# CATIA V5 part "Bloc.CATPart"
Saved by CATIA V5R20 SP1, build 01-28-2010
Part number: Bloc
Bounding box of the stored display mesh (mm): x -115 to 115, y -115 to 115, z -20 to 0
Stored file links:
  C:\Users\Nikow\Documents\IAO\Bloc.CATPart
  C:\Users\Nikow\Documents\IAO\Mecanisme_a_bielle_et_deux_coulisseaux.CATProduct
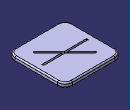
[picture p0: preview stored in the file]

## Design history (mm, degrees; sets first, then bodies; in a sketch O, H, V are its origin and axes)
External parameters (linked from other documents)
  External.Longueur_gliss = 170 mm
  External.Largeur = 7 mm
  External.Epaisseur = 20 mm
Set1
  Plane1 "Plan_de_ref": linked copy from another document
  Point1 to Point4: linked copy from another document
Body1 (main body)
  Sketch1 on Plane1, origin (0, 0, 0), H (1, 0, 0), V (0, 1, 0)
    line L1 (-115, -85) -> (-115, 85)
    arc A1 centre (-85, 85) radius 30 from (-115, 85) to (-85, 115) cw
    line L2 (-85, 115) -> (85, 115)
    arc A2 centre (85, 85) radius 30 from (85, 115) to (115, 85) cw
    line L3 (115, 85) -> (115, -85)
    arc A3 centre (85, -85) radius 30 from (115, -85) to (85, -115) cw
    line L4 (85, -115) -> (-85, -115)
    arc A4 centre (-85, -85) radius 30 from (-85, -115) to (-115, -85) cw
    point P13 (-88, 3.5)
    line L5 (-88, 3.5) -> (-8.4497, 3.5)
    line L6 (-8.4497, 3.5) -> (-64.7003, 59.7505)
    point P15 (-64.7003, 59.7505)
    point P16 (-59.7505, 64.7003)
    line L7 (-59.7505, 64.7003) -> (1.4497, 3.5)
    line L8 (1.4497, 3.5) -> (88, 3.5)
    point P18 (88, 3.5)
    point P19 (88, -3.5)
    line L9 (88, -3.5) -> (8.4497, -3.5)
    line L10 (8.4497, -3.5) -> (64.7003, -59.7505)
    point P21 (64.7003, -59.7505)
    point P22 (59.7505, -64.7003)
    line L11 (59.7505, -64.7003) -> (-1.4497, -3.5)
    line L12 (-1.4497, -3.5) -> (-88, -3.5)
    point P24 (-88, -3.5)
    arc A5 centre (-63.2861, 61.1647) radius 2 from (-64.7003, 62.579) to (-64.7003, 59.7505) ccw
    point P27 (-64.7003, 59.7505)
    line L13 (-64.7003, 62.579) -> (-62.579, 64.7003)
    arc A6 centre (-61.1647, 63.2861) radius 2 from (-59.7505, 64.7003) to (-62.579, 64.7003) ccw
    point P30 (-59.7505, 64.7003)
    reference projected point E1 (-60.1041, 60.1041) from Point2
    line L14 (64.7003, -62.579) -> (62.579, -64.7003)
    arc A7 centre (61.1647, -63.2861) radius 2 from (62.579, -64.7003) to (59.7505, -64.7003) cw
    point P34 (59.7505, -64.7003)
    arc A8 centre (63.2861, -61.1647) radius 2 from (64.7003, -62.579) to (64.7003, -59.7505) ccw
    point P36 (64.7003, -59.7505)
    reference projected point E2 (60.1041, -60.1041) from Point4
    arc A9 centre (88, 1.5) radius 2 from (90, 1.5) to (88, 3.5) ccw
    point P39 (88, 3.5)
    line L15 (90, 1.5) -> (90, -1.5)
    arc A10 centre (88, -1.5) radius 2 from (88, -3.5) to (90, -1.5) ccw
    point P42 (88, -3.5)
    reference projected point E3 (85, 0) from Point3
    arc A11 centre (-88, 1.5) radius 2 from (-88, 3.5) to (-90, 1.5) ccw
    point P44 (-88, 3.5)
    line L16 (-90, 1.5) -> (-90, -1.5)
    arc A12 centre (-88, -1.5) radius 2 from (-90, -1.5) to (-88, -3.5) ccw
    point P48 (-88, -3.5)
    reference projected point E4 (-85, 0) from Point1
    length L2 = 170 {= External.Longueur_gliss}
    length L3 = 170 {= External.Longueur_gliss}
    radius A2 = 30
    radius A1 = 30
    length L1 = 170 {= External.Longueur_gliss}
    length L4 = 170 {= External.Longueur_gliss}
    radius A4 = 30
    radius A3 = 30
    distance L1 V = 115 {= External.Longueur_gliss/2 +30mm}
    distance L2 H = 115 {= External.Longueur_gliss /2+30mm}
    distance L12 L5 = 7 {= External.Largeur}
    distance L8 L9 = 7 {= External.Largeur}
    distance L10 L11 = 7 {= External.Largeur}
    distance L7 L6 = 7 {= External.Largeur}
    radius A6 = 2
    radius A5 = 2
    distance E1 L13 = 5
    radius A8 = 2
    radius A7 = 2
    distance E2 L14 = 5
    radius A10 = 2
    radius A9 = 2
    distance E3 L15 = 5
    radius A12 = 2
    radius A11 = 2
    distance L16 E4 = 5
    vertical: L1 V
    tangency: A1 L1, L2 A1, A2 L2, L3 A2, A3 L3, L4 A3, A4 L1, A4 L4, L13 A6, A6 L7, A5 L13, A5 L6, A7 L14, L14 A8, A7 L11, A8 L10, A10 L15, A9 L8, A10 L9, L15 A9, L16 A11, A11 L5, A12 L12, A12 L16
    horizontal: L2 H, L5 H, L12 H, L9 H, L8 H
    parallelism: L11 L6
    coincidence: P30 P16, P27 P15, P36 P21, P34 P22, A9 P18, P39 P18, P42 P19, P48 P24, P44 P13
    perpendicularity: L13 L7, L14 L10, L15 L8, L16 L12
  Pad1: profile Sketch1, direction (0, 0, -1), length 20 {= External.Epaisseur}
  Fillet1: radius 5, on edge [face of Pad1 from Sketch1.L2 | start face of Pad1]; edge [end face of Pad1 | face of Pad1 from Sketch1.L2]
Relations
  Sketch1.distance(L1 V) = `Paramètres externes\Longueur_gliss` /2+30MM (deactivated)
